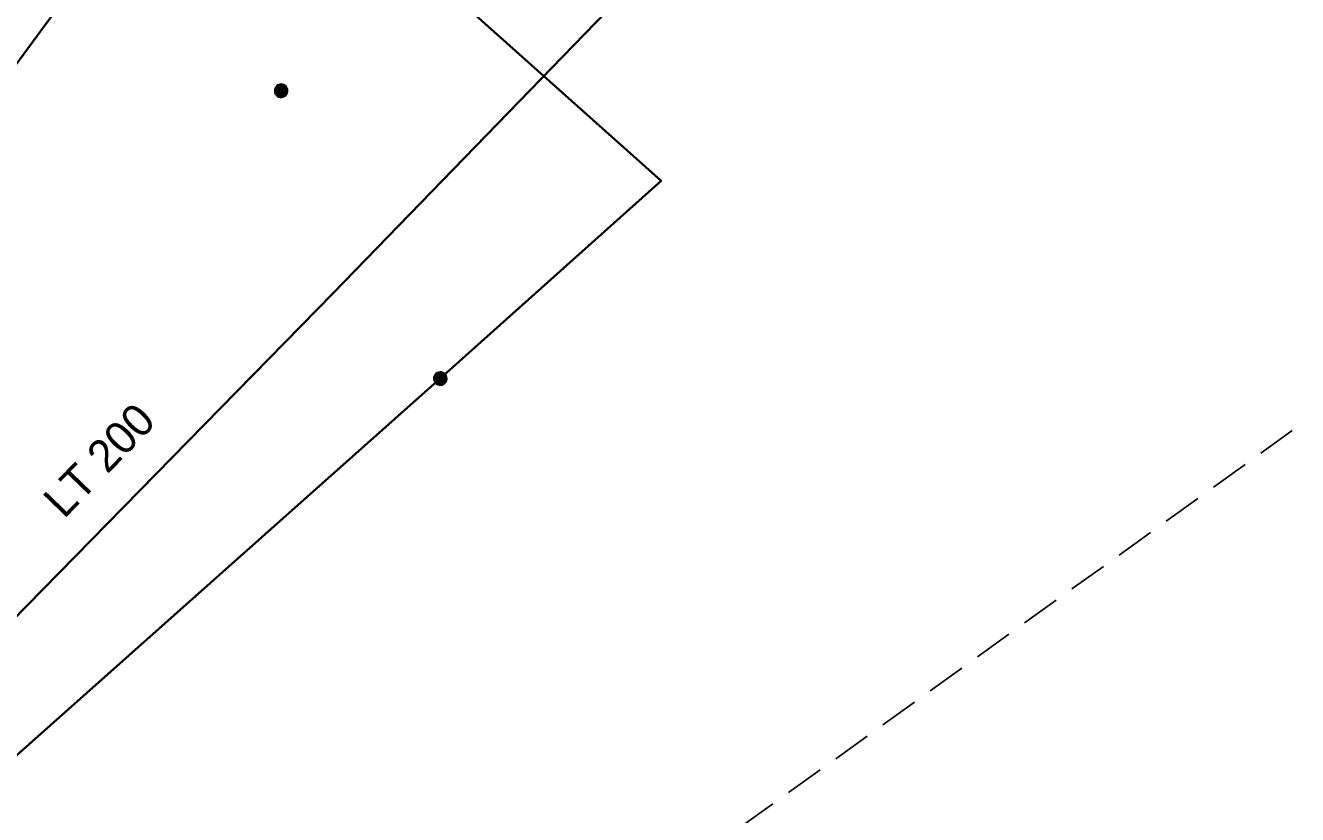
# Model space of a CAD drawing. Extents: x -867104 to -866746, y -1014489 to -1014255.
# Drawn here: x -866865.74 to -866822.42, y -1014458.07 to -1014431.21 of the extents above; entities that cross this region are included whole.
import ezdxf

# ---------------------------------------------------------------- set-up
doc = ezdxf.new("R2010")
doc.units = 0
doc.header["$LTSCALE"] = 0.44
doc.linetypes.add('MEDIUM_DASHED', pattern=[4.5, 3, -1.5])
for name, color, linetype, lineweight in [('1', 7, 'Continuous', 35), ('21', 7, 'Continuous', 35), ('32', 7, 'Continuous', 13), ('62', 7, 'MEDIUM_DASHED', 25)]:
    doc.layers.add(name, color=color, linetype=linetype, lineweight=lineweight)

msp = doc.modelspace()

# ---------------------------------------------------------------- linework, layer by layer
at = {"layer": '1'}
for points in [[(-866840.01, -1014396.11), (-866844.69, -1014400.78), (-866847.06, -1014402.96), (-866848.88, -1014406.15), (-866860.28, -1014424.67), (-866871.77, -1014440.29), (-866875.11, -1014444.27), (-866876.93, -1014446.09), (-866879, -1014449.37), (-866879.17, -1014450.73), (-866879.17, -1014451.68), (-866879.03, -1014452.53), (-866876.52, -1014455.41), (-866874.72, -1014458.69), (-866874.8, -1014459.33), (-866875.66, -1014460.47), (-866876.85, -1014461.77), (-866877.992, -1014463.135), (-866881.12, -1014466.73), (-866885.53, -1014471.37), (-866892.467, -1014476.423)], [(-866829.29, -1014413.39), (-866837.14, -1014421.79), (-866844.09, -1014428.8), (-866855.26, -1014440.32), (-866867.329, -1014452.641), (-866873.974, -1014459.295), (-866875.079, -1014460.444), (-866876.617, -1014462.044), (-866877.133, -1014462.581), (-866877.679, -1014463.149)]]:
    msp.add_lwpolyline(points, dxfattribs=at)
at = {"layer": '21'}
msp.add_line((-866867.31, -1014457.18), (-866851.61, -1014443.23), dxfattribs=at)
msp.add_lwpolyline([(-866851.61, -1014443.23), (-866844.093, -1014436.497), (-866861.15, -1014421.261)], dxfattribs=at)
at = {"layer": '32'}
for points in [[(-866856.799, -1014433.43), (-866856.805, -1014433.378), (-866856.822, -1014433.328), (-866856.851, -1014433.284), (-866856.888, -1014433.247), (-866856.933, -1014433.22), (-866856.983, -1014433.203), (-866857.036, -1014433.199), (-866857.088, -1014433.206), (-866857.137, -1014433.225), (-866857.18, -1014433.254), (-866857.216, -1014433.293), (-866857.242, -1014433.338), (-866857.258, -1014433.389), (-866857.261, -1014433.441), (-866857.253, -1014433.493), (-866857.233, -1014433.542), (-866857.202, -1014433.585), (-866857.163, -1014433.619), (-866857.117, -1014433.645), (-866857.066, -1014433.659), (-866857.013, -1014433.661), (-866856.962, -1014433.651), (-866856.914, -1014433.63), (-866856.871, -1014433.599), (-866856.837, -1014433.558), (-866856.813, -1014433.512), (-866856.801, -1014433.461)], [(-866856.829, -1014433.43), (-866856.835, -1014433.381), (-866856.852, -1014433.335), (-866856.88, -1014433.295), (-866856.917, -1014433.263), (-866856.961, -1014433.241), (-866857.009, -1014433.23), (-866857.058, -1014433.23), (-866857.105, -1014433.243), (-866857.148, -1014433.267), (-866857.184, -1014433.3), (-866857.211, -1014433.341), (-866857.227, -1014433.388), (-866857.231, -1014433.437), (-866857.224, -1014433.485), (-866857.205, -1014433.53), (-866857.175, -1014433.57), (-866857.137, -1014433.601), (-866857.093, -1014433.621), (-866857.045, -1014433.631), (-866856.996, -1014433.629), (-866856.949, -1014433.614), (-866856.906, -1014433.589), (-866856.872, -1014433.555), (-866856.846, -1014433.513), (-866856.832, -1014433.466)], [(-866856.859, -1014433.43), (-866856.865, -1014433.385), (-866856.882, -1014433.343), (-866856.91, -1014433.308), (-866856.946, -1014433.281), (-866856.988, -1014433.264), (-866857.033, -1014433.259), (-866857.078, -1014433.265), (-866857.119, -1014433.284), (-866857.154, -1014433.312), (-866857.181, -1014433.349), (-866857.197, -1014433.391), (-866857.201, -1014433.436), (-866857.194, -1014433.481), (-866857.175, -1014433.522), (-866857.146, -1014433.556), (-866857.109, -1014433.582), (-866857.066, -1014433.598), (-866857.021, -1014433.601), (-866856.976, -1014433.593), (-866856.936, -1014433.573), (-866856.902, -1014433.544), (-866856.876, -1014433.506), (-866856.862, -1014433.463)], [(-866856.889, -1014433.43), (-866856.894, -1014433.389), (-866856.912, -1014433.352), (-866856.939, -1014433.321), (-866856.974, -1014433.3), (-866857.014, -1014433.289), (-866857.055, -1014433.291), (-866857.094, -1014433.304), (-866857.128, -1014433.328), (-866857.153, -1014433.36), (-866857.168, -1014433.398), (-866857.171, -1014433.439), (-866857.163, -1014433.479), (-866857.143, -1014433.515), (-866857.114, -1014433.544), (-866857.077, -1014433.563), (-866857.037, -1014433.571), (-866856.996, -1014433.567), (-866856.958, -1014433.552), (-866856.926, -1014433.526), (-866856.903, -1014433.492), (-866856.89, -1014433.453)], [(-866856.919, -1014433.43), (-866856.924, -1014433.394), (-866856.942, -1014433.362), (-866856.968, -1014433.337), (-866857.002, -1014433.322), (-866857.038, -1014433.319), (-866857.073, -1014433.327), (-866857.104, -1014433.347), (-866857.127, -1014433.375), (-866857.14, -1014433.409), (-866857.14, -1014433.446), (-866857.129, -1014433.481), (-866857.108, -1014433.51), (-866857.078, -1014433.531), (-866857.043, -1014433.541), (-866857.006, -1014433.539), (-866856.972, -1014433.525), (-866856.945, -1014433.502), (-866856.926, -1014433.47), (-866856.919, -1014433.435)], [(-866856.949, -1014433.43), (-866856.954, -1014433.399), (-866856.971, -1014433.373), (-866856.997, -1014433.356), (-866857.027, -1014433.349), (-866857.058, -1014433.353), (-866857.085, -1014433.37), (-866857.103, -1014433.394), (-866857.111, -1014433.425), (-866857.107, -1014433.455), (-866857.092, -1014433.483), (-866857.068, -1014433.502), (-866857.038, -1014433.511), (-866857.007, -1014433.508), (-866856.979, -1014433.494), (-866856.959, -1014433.47), (-866856.949, -1014433.441)], [(-866856.979, -1014433.43), (-866856.984, -1014433.406), (-866857.001, -1014433.388), (-866857.024, -1014433.379), (-866857.048, -1014433.382), (-866857.069, -1014433.396), (-866857.08, -1014433.418), (-866857.08, -1014433.443), (-866857.068, -1014433.464), (-866857.048, -1014433.478), (-866857.023, -1014433.481), (-866857, -1014433.472), (-866856.984, -1014433.454)], [(-866857.009, -1014433.43), (-866857.014, -1014433.415), (-866857.029, -1014433.409), (-866857.044, -1014433.413), (-866857.051, -1014433.427), (-866857.047, -1014433.442), (-866857.034, -1014433.451), (-866857.019, -1014433.448), (-866857.009, -1014433.436)], [(-866851.379, -1014443.23), (-866851.385, -1014443.178), (-866851.402, -1014443.128), (-866851.431, -1014443.084), (-866851.468, -1014443.047), (-866851.513, -1014443.02), (-866851.563, -1014443.003), (-866851.616, -1014442.999), (-866851.668, -1014443.006), (-866851.717, -1014443.025), (-866851.76, -1014443.054), (-866851.796, -1014443.093), (-866851.822, -1014443.138), (-866851.838, -1014443.189), (-866851.841, -1014443.241), (-866851.833, -1014443.293), (-866851.813, -1014443.342), (-866851.782, -1014443.385), (-866851.743, -1014443.419), (-866851.697, -1014443.445), (-866851.646, -1014443.459), (-866851.593, -1014443.461), (-866851.542, -1014443.451), (-866851.494, -1014443.43), (-866851.451, -1014443.399), (-866851.417, -1014443.358), (-866851.393, -1014443.312), (-866851.38, -1014443.261)], [(-866851.409, -1014443.23), (-866851.415, -1014443.181), (-866851.432, -1014443.135), (-866851.46, -1014443.095), (-866851.497, -1014443.063), (-866851.541, -1014443.041), (-866851.589, -1014443.03), (-866851.638, -1014443.03), (-866851.684, -1014443.043), (-866851.728, -1014443.067), (-866851.764, -1014443.1), (-866851.791, -1014443.141), (-866851.807, -1014443.188), (-866851.811, -1014443.237), (-866851.804, -1014443.285), (-866851.785, -1014443.33), (-866851.755, -1014443.37), (-866851.717, -1014443.401), (-866851.673, -1014443.421), (-866851.625, -1014443.431), (-866851.576, -1014443.429), (-866851.529, -1014443.414), (-866851.486, -1014443.389), (-866851.451, -1014443.355), (-866851.426, -1014443.313), (-866851.412, -1014443.266)], [(-866851.439, -1014443.23), (-866851.445, -1014443.185), (-866851.462, -1014443.143), (-866851.49, -1014443.108), (-866851.526, -1014443.081), (-866851.568, -1014443.064), (-866851.613, -1014443.059), (-866851.657, -1014443.065), (-866851.699, -1014443.084), (-866851.733, -1014443.112), (-866851.761, -1014443.149), (-866851.777, -1014443.191), (-866851.781, -1014443.236), (-866851.774, -1014443.281), (-866851.755, -1014443.322), (-866851.726, -1014443.356), (-866851.689, -1014443.382), (-866851.646, -1014443.398), (-866851.601, -1014443.401), (-866851.556, -1014443.393), (-866851.516, -1014443.373), (-866851.482, -1014443.344), (-866851.456, -1014443.306), (-866851.442, -1014443.263)], [(-866851.469, -1014443.23), (-866851.473, -1014443.189), (-866851.492, -1014443.152), (-866851.519, -1014443.121), (-866851.554, -1014443.1), (-866851.594, -1014443.089), (-866851.635, -1014443.091), (-866851.674, -1014443.104), (-866851.708, -1014443.128), (-866851.733, -1014443.16), (-866851.748, -1014443.198), (-866851.75, -1014443.239), (-866851.743, -1014443.279), (-866851.723, -1014443.315), (-866851.694, -1014443.344), (-866851.657, -1014443.363), (-866851.617, -1014443.371), (-866851.576, -1014443.367), (-866851.538, -1014443.352), (-866851.505, -1014443.326), (-866851.483, -1014443.292), (-866851.47, -1014443.253)], [(-866851.499, -1014443.23), (-866851.504, -1014443.194), (-866851.522, -1014443.162), (-866851.548, -1014443.137), (-866851.581, -1014443.122), (-866851.618, -1014443.119), (-866851.652, -1014443.127), (-866851.684, -1014443.147), (-866851.706, -1014443.175), (-866851.72, -1014443.209), (-866851.72, -1014443.246), (-866851.709, -1014443.281), (-866851.688, -1014443.31), (-866851.657, -1014443.331), (-866851.623, -1014443.341), (-866851.586, -1014443.339), (-866851.552, -1014443.325), (-866851.525, -1014443.302), (-866851.505, -1014443.27), (-866851.499, -1014443.235)], [(-866851.529, -1014443.23), (-866851.534, -1014443.199), (-866851.551, -1014443.173), (-866851.576, -1014443.156), (-866851.607, -1014443.149), (-866851.638, -1014443.153), (-866851.665, -1014443.17), (-866851.683, -1014443.194), (-866851.691, -1014443.225), (-866851.687, -1014443.255), (-866851.672, -1014443.283), (-866851.647, -1014443.302), (-866851.618, -1014443.311), (-866851.587, -1014443.308), (-866851.559, -1014443.294), (-866851.539, -1014443.27), (-866851.529, -1014443.241)], [(-866851.559, -1014443.23), (-866851.564, -1014443.206), (-866851.581, -1014443.188), (-866851.603, -1014443.179), (-866851.628, -1014443.182), (-866851.649, -1014443.196), (-866851.66, -1014443.218), (-866851.66, -1014443.243), (-866851.647, -1014443.264), (-866851.628, -1014443.278), (-866851.603, -1014443.281), (-866851.58, -1014443.272), (-866851.564, -1014443.254)], [(-866851.589, -1014443.23), (-866851.594, -1014443.215), (-866851.608, -1014443.209), (-866851.624, -1014443.213), (-866851.63, -1014443.227), (-866851.627, -1014443.242), (-866851.614, -1014443.251), (-866851.598, -1014443.248), (-866851.589, -1014443.236)]]:
    msp.add_lwpolyline(points, close=True, dxfattribs=at)
at = {"layer": '62'}
msp.add_lwpolyline([(-867100.742, -1014391.242), (-867092.704, -1014271.063), (-867058.137, -1014262.221), (-866832.652, -1014254.584), (-866798.889, -1014276.691), (-866769.95, -1014301.209), (-866746.236, -1014362.705), (-866806.526, -1014433.445), (-866883.697, -1014488.912), (-866958.859, -1014435.455)], close=True, dxfattribs=at)

# ---------------------------------------------------------------- texts
at = {"layer": '1'}
msp.add_text('LT 200', height=1.1, rotation=46, dxfattribs=at).set_placement((-866864.424, -1014448.032))

doc.saveas('drawing.dxf')
